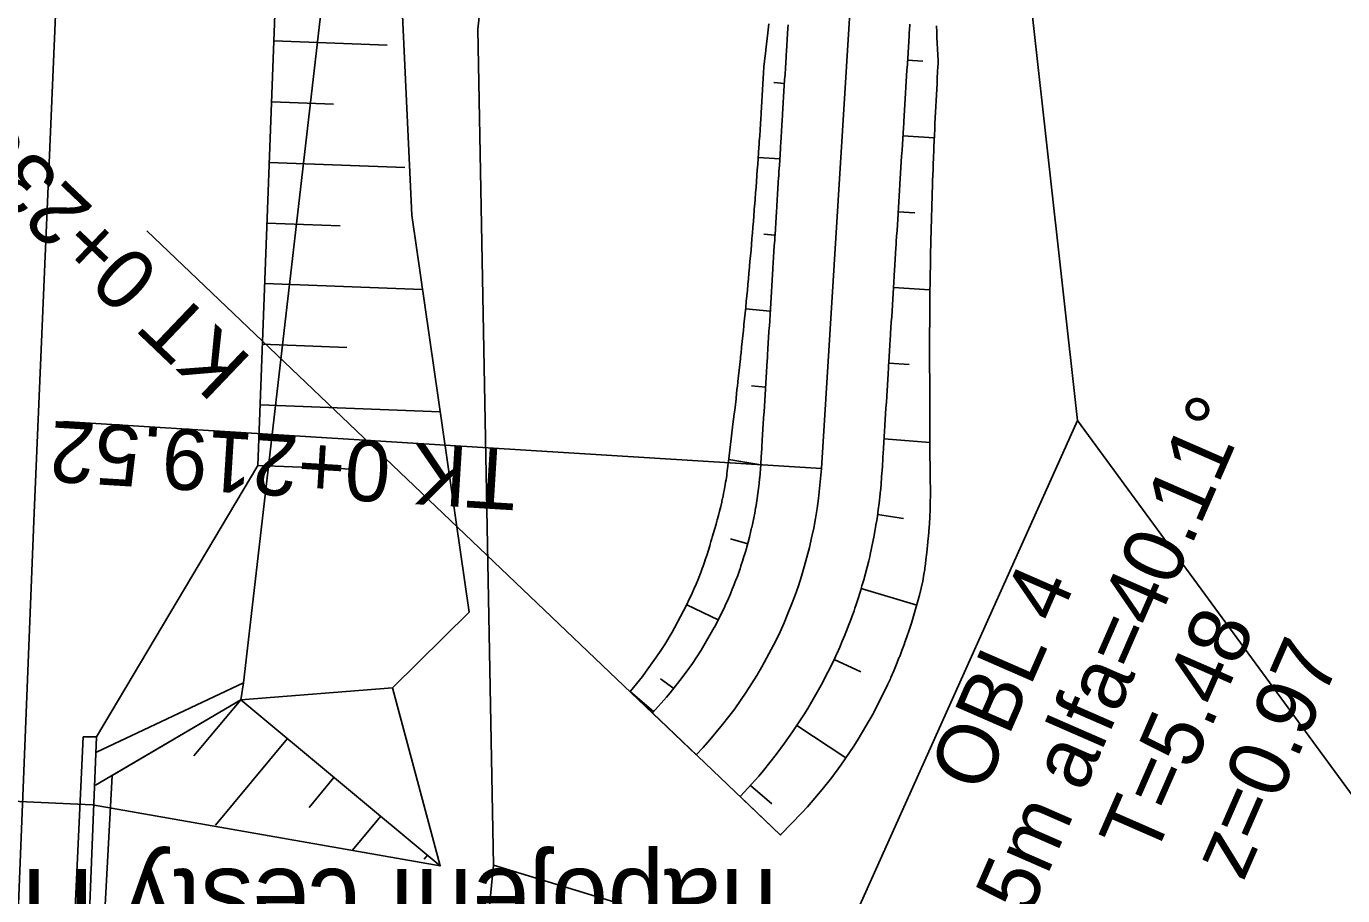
# Model space of a CAD drawing. Extents: x -583470 to -583050, y -1165714 to -1165417.
# Drawn here: x -583387.17 to -583343.82, y -1165639.09 to -1165610.45 of the extents above; entities that cross this region are included whole.
import ezdxf

# ---------------------------------------------------------------- set-up
doc = ezdxf.new("R2010")
doc.units = 0
for name, color, linetype in [('22', 7, 'Continuous'), ('40', 7, 'Continuous'), ('42', 7, 'Continuous'), ('60', 7, 'Continuous'), ('62', 7, 'Continuous'), ('Hranice parcel', 7, 'Continuous'), ('Parcelní čísla', 7, 'Continuous'), ('Rám', 7, 'Continuous'), ('Sítě', 7, 'Continuous'), ('Šrafy', 7, 'Continuous')]:
    doc.layers.add(name, color=color, linetype=linetype)

msp = doc.modelspace()

# ---------------------------------------------------------------- linework, layer by layer
at = {"layer": '22'}
for points in [[(-583384.86, -1165634.36), (-583380.02, -1165632.08), (-583380.11, -1165632.63), (-583384.89, -1165635.45)], [(-583385.3, -1165633.85), (-583384.86, -1165633.85), (-583385.19, -1165642.1), (-583385.68, -1165642.08), (-583385.3, -1165633.85)], [(-583384.99, -1165636.09), (-583389.58, -1165635.88)]]:
    msp.add_lwpolyline(points, dxfattribs=at)
at = {"layer": '40'}
msp.add_lwpolyline([(-583380.11, -1165632.63), (-583375.11, -1165632.24)], dxfattribs=at)
at = {"layer": '42'}
for points in [[(-583384.86, -1165633.85), (-583379.55, -1165624.92), (-583378.83, -1165605.97), (-583382.33, -1165599.28), (-583381.32, -1165575.74)], [(-583384.99, -1165636.09), (-583373.54, -1165638.1), (-583375.11, -1165632.24), (-583372.59, -1165629.75), (-583374.48, -1165616.67), (-583375, -1165605.38), (-583378.65, -1165593.33), (-583377.9, -1165588.81)], [(-583380.11, -1165632.63), (-583373.54, -1165638.1)]]:
    msp.add_lwpolyline(points, dxfattribs=at)
at = {"layer": '60'}
for points in [[(-583379.02, -1165610.93), (-583375.29, -1165611.07)], [(-583379.09, -1165612.93), (-583377.05, -1165613.01)], [(-583379.17, -1165614.93), (-583374.71, -1165615.1)], [(-583379.25, -1165616.93), (-583376.83, -1165617.02)], [(-583379.32, -1165618.92), (-583374.13, -1165619.12)], [(-583379.4, -1165620.92), (-583376.62, -1165621.03)], [(-583379.47, -1165622.92), (-583373.54, -1165623.15)], [(-583379.55, -1165624.92), (-583376.4, -1165625.04)], [(-583380.11, -1165632.63), (-583381.65, -1165634.48)], [(-583378.57, -1165633.91), (-583380.94, -1165636.76)], [(-583377.04, -1165635.19), (-583377.86, -1165636.18)], [(-583375.5, -1165636.47), (-583376.44, -1165637.6)], [(-583373.96, -1165637.75), (-583374.07, -1165637.88)]]:
    msp.add_lwpolyline(points, dxfattribs=at)
at = {"layer": '62'}
for points in [[(-583379.741, -1165694.56), (-583379.57, -1165690.87), (-583377.81, -1165675.52), (-583374, -1165654.25), (-583372.12, -1165641.43), (-583371.79, -1165638.08), (-583372.3, -1165610.54), (-583370.49, -1165593.91), (-583364.41, -1165578.01), (-583353.13, -1165562.49), (-583348.06, -1165556.64), (-583342.86, -1165548.6), (-583339.71, -1165538.95), (-583338.99, -1165532.81), (-583338.38, -1165526.75), (-583340.63, -1165516.91), (-583347.05, -1165504.24), (-583349.624, -1165498.549)], [(-583371.79, -1165638.08), (-583361.74, -1165641.15), (-583346.91, -1165644.58), (-583323.24, -1165647.92), (-583297.05, -1165651.52), (-583281.69, -1165654.07), (-583264.82, -1165656.96), (-583238.56, -1165662.27)]]:
    msp.add_lwpolyline(points, dxfattribs=at)
at = {"layer": 'Hranice parcel'}
for points in [[(-583365.111, -1165634.443), (-583383.196, -1165617.183)], [(-583360.991, -1165625.018), (-583385.943, -1165623.467)]]:
    msp.add_lwpolyline(points, dxfattribs=at)
at = {"layer": 'Parcelní čísla'}
msp.add_line((-583359.64, -1165603.276), (-583360.991, -1165625.018), dxfattribs=at)
msp.add_arc((-583375.962, -1165624.087), 15, 316.3365, 356.4435, dxfattribs=at)
at = {"layer": 'Rám'}
for points in [[(-583202.69, -1165538.68), (-583225.12, -1165531.51), (-583247.31, -1165545.19), (-583283.21, -1165574.06), (-583292.71, -1165580.22), (-583304.73, -1165581.14), (-583316.86, -1165578.96), (-583335.26, -1165581.29), (-583341.42, -1165583.09), (-583347.21, -1165586.62), (-583351.13, -1165592.35), (-583353.34, -1165595.85), (-583354.98, -1165601.64), (-583352.56, -1165623.43)], [(-583372.44, -1165649.28), (-583380.56, -1165643.71), (-583384.65, -1165640.82), (-583384.34, -1165635.13), (-583380.11, -1165632.63), (-583380.02, -1165632.08), (-583374.92, -1165587.93), (-583361.04, -1165570.69)], [(-583372.44, -1165649.28), (-583361.47, -1165643.29), (-583352.56, -1165623.43)], [(-583352.56, -1165623.43), (-583338.23, -1165642.98), (-583317.68, -1165646.22), (-583282.91, -1165650.36), (-583267.19, -1165652.43), (-583242.28, -1165656.94), (-583228.69, -1165666.2)]]:
    msp.add_lwpolyline(points, dxfattribs=at)
at = {"layer": 'Sítě'}
for points in [[(-583357.201, -1165610.434), (-583357.192, -1165610.624), (-583357.188, -1165610.705), (-583357.183, -1165610.814), (-583357.174, -1165611.004), (-583357.164, -1165611.194), (-583357.155, -1165611.384), (-583357.145, -1165611.574), (-583357.147, -1165611.709), (-583357.15, -1165611.763), (-583357.161, -1165611.952), (-583357.172, -1165612.14), (-583357.182, -1165612.329), (-583357.193, -1165612.518), (-583357.203, -1165612.708), (-583357.213, -1165612.896), (-583357.223, -1165613.084), (-583357.232, -1165613.273), (-583357.241, -1165613.462), (-583357.25, -1165613.651), (-583357.253, -1165613.707), (-583357.259, -1165613.84), (-583357.268, -1165614.029), (-583357.276, -1165614.218), (-583357.284, -1165614.407), (-583357.292, -1165614.596), (-583357.296, -1165614.706), (-583357.3, -1165614.785), (-583357.307, -1165614.974), (-583357.314, -1165615.163), (-583357.321, -1165615.352), (-583357.328, -1165615.541), (-583357.334, -1165615.705), (-583357.335, -1165615.73), (-583357.341, -1165615.919), (-583357.347, -1165616.108), (-583357.353, -1165616.297), (-583357.358, -1165616.486), (-583357.364, -1165616.675), (-583357.365, -1165616.705), (-583357.369, -1165616.864), (-583357.374, -1165617.053), (-583357.379, -1165617.242), (-583357.383, -1165617.431), (-583357.388, -1165617.621), (-583357.389, -1165617.706), (-583357.392, -1165617.81), (-583357.395, -1165617.999), (-583357.399, -1165618.188), (-583357.402, -1165618.377), (-583357.406, -1165618.567), (-583357.408, -1165618.707), (-583357.409, -1165618.756), (-583357.411, -1165618.945), (-583357.414, -1165619.135), (-583357.416, -1165619.324), (-583357.418, -1165619.513), (-583357.42, -1165619.708), (-583357.421, -1165619.892), (-583357.423, -1165620.081), (-583357.424, -1165620.271), (-583357.425, -1165620.46), (-583357.426, -1165620.649), (-583357.426, -1165620.709), (-583357.426, -1165620.839), (-583357.426, -1165621.028), (-583357.426, -1165621.218), (-583357.426, -1165621.407), (-583357.426, -1165621.596), (-583357.425, -1165621.711), (-583357.425, -1165621.786), (-583357.424, -1165621.975), (-583357.423, -1165622.165), (-583357.422, -1165622.354), (-583357.42, -1165622.544), (-583357.42, -1165622.714), (-583357.42, -1165622.733), (-583357.421, -1165622.923), (-583357.421, -1165623.112), (-583357.421, -1165623.302), (-583357.421, -1165623.491), (-583357.42, -1165623.681), (-583357.42, -1165623.716), (-583357.42, -1165623.87), (-583357.419, -1165624.06), (-583357.418, -1165624.249), (-583357.416, -1165624.439), (-583357.415, -1165624.628), (-583357.414, -1165624.718), (-583357.413, -1165624.818), (-583357.411, -1165625.007), (-583357.408, -1165625.197), (-583357.408, -1165625.24), (-583357.404, -1165625.422), (-583357.401, -1165625.657), (-583357.401, -1165625.837), (-583357.401, -1165625.893), (-583357.405, -1165626.129), (-583357.408, -1165626.248), (-583357.411, -1165626.366), (-583357.421, -1165626.602), (-583357.434, -1165626.839), (-583357.45, -1165627.075), (-583357.45, -1165627.087), (-583357.464, -1165627.258), (-583357.469, -1165627.312), (-583357.491, -1165627.548), (-583357.516, -1165627.785), (-583357.545, -1165628.021), (-583357.577, -1165628.257), (-583357.578, -1165628.268), (-583357.588, -1165628.338), (-583357.612, -1165628.493), (-583357.651, -1165628.729), (-583357.705, -1165628.961), (-583357.763, -1165629.192), (-583357.782, -1165629.265), (-583357.824, -1165629.422), (-583357.864, -1165629.567), (-583357.888, -1165629.652), (-583357.955, -1165629.881), (-583358.026, -1165630.109), (-583358.068, -1165630.242), (-583358.099, -1165630.336), (-583358.175, -1165630.562), (-583358.248, -1165630.768), (-583358.255, -1165630.787), (-583358.338, -1165631.01), (-583358.411, -1165631.202), (-583358.423, -1165631.233), (-583358.512, -1165631.455), (-583358.604, -1165631.675), (-583358.699, -1165631.895), (-583358.719, -1165631.94), (-583358.81, -1165632.141), (-583359.265, -1165633.054), (-583359.276, -1165633.073), (-583359.777, -1165633.936), (-583359.919, -1165634.16), (-583360.344, -1165634.784), (-583360.645, -1165635.192), (-583360.962, -1165635.594), (-583361.449, -1165636.164), (-583361.629, -1165636.362), (-583362.324, -1165637.067), (-583362.343, -1165637.085), (-583367.289, -1165632.364), (-583367.278, -1165632.352), (-583366.884, -1165631.862), (-583366.781, -1165631.726), (-583366.504, -1165631.343), (-583366.322, -1165631.076), (-583366.149, -1165630.808), (-583365.903, -1165630.403), (-583365.821, -1165630.259), (-583365.525, -1165629.708), (-583365.519, -1165629.696), (-583365.244, -1165629.12), (-583365.188, -1165628.994), (-583365.176, -1165628.965), (-583365.117, -1165628.828), (-583365.06, -1165628.69), (-583365.005, -1165628.552), (-583364.997, -1165628.532), (-583364.951, -1165628.412), (-583364.899, -1165628.273), (-583364.895, -1165628.261), (-583364.849, -1165628.132), (-583364.801, -1165627.991), (-583364.782, -1165627.933), (-583364.754, -1165627.85), (-583364.709, -1165627.708), (-583364.666, -1165627.565), (-583364.65, -1165627.512), (-583364.625, -1165627.422), (-583364.597, -1165627.324), (-583364.585, -1165627.278), (-583364.547, -1165627.134), (-583364.502, -1165626.992), (-583364.459, -1165626.849), (-583364.432, -1165626.754), (-583364.418, -1165626.706), (-583364.379, -1165626.561), (-583364.341, -1165626.417), (-583364.305, -1165626.271), (-583364.271, -1165626.126), (-583364.264, -1165626.092), (-583364.241, -1165625.987), (-583364.239, -1165625.979), (-583364.209, -1165625.832), (-583364.181, -1165625.685), (-583364.154, -1165625.537), (-583364.142, -1165625.463), (-583364.13, -1165625.389), (-583364.107, -1165625.241), (-583364.102, -1165625.205), (-583364.087, -1165625.092), (-583364.068, -1165624.942), (-583364.055, -1165624.827), (-583364.05, -1165624.784), (-583364.026, -1165624.596), (-583364.003, -1165624.408), (-583363.99, -1165624.309), (-583363.98, -1165624.22), (-583363.957, -1165624.032), (-583363.934, -1165623.844), (-583363.911, -1165623.656), (-583363.889, -1165623.468), (-583363.871, -1165623.315), (-583363.867, -1165623.28), (-583363.845, -1165623.092), (-583363.823, -1165622.904), (-583363.801, -1165622.716), (-583363.78, -1165622.528), (-583363.759, -1165622.339), (-583363.756, -1165622.32), (-583363.738, -1165622.151), (-583363.717, -1165621.963), (-583363.696, -1165621.775), (-583363.676, -1165621.587), (-583363.655, -1165621.399), (-583363.648, -1165621.325), (-583363.635, -1165621.211), (-583363.616, -1165621.022), (-583363.596, -1165620.834), (-583363.576, -1165620.646), (-583363.557, -1165620.458), (-583363.544, -1165620.329), (-583363.538, -1165620.269), (-583363.519, -1165620.081), (-583363.5, -1165619.893), (-583363.482, -1165619.705), (-583363.463, -1165619.516), (-583363.445, -1165619.328), (-583363.427, -1165619.14), (-583363.41, -1165618.951), (-583363.392, -1165618.763), (-583363.375, -1165618.575), (-583363.358, -1165618.386), (-583363.353, -1165618.337), (-583363.341, -1165618.198), (-583363.324, -1165618.009), (-583363.307, -1165617.821), (-583363.291, -1165617.633), (-583363.275, -1165617.444), (-583363.267, -1165617.341), (-583363.26, -1165617.256), (-583363.244, -1165617.067), (-583363.229, -1165616.879), (-583363.214, -1165616.69), (-583363.199, -1165616.502), (-583363.187, -1165616.344), (-583363.184, -1165616.313), (-583363.17, -1165616.125), (-583363.155, -1165615.936), (-583363.141, -1165615.748), (-583363.127, -1165615.559), (-583363.113, -1165615.37), (-583363.111, -1165615.346), (-583363.099, -1165615.182), (-583363.086, -1165614.993), (-583363.073, -1165614.805), (-583363.059, -1165614.616), (-583363.047, -1165614.427), (-583363.041, -1165614.349), (-583363.034, -1165614.239), (-583363.021, -1165614.05), (-583363.009, -1165613.861), (-583362.997, -1165613.673), (-583362.985, -1165613.484), (-583362.976, -1165613.351), (-583362.973, -1165613.295), (-583362.961, -1165613.107), (-583362.95, -1165612.918), (-583362.938, -1165612.729), (-583362.927, -1165612.54), (-583362.916, -1165612.352), (-583362.906, -1165612.163), (-583362.895, -1165611.974), (-583362.883, -1165611.785), (-583362.863, -1165611.597), (-583362.841, -1165611.409), (-583362.835, -1165611.356), (-583362.819, -1165611.221), (-583362.798, -1165611.033), (-583362.776, -1165610.845), (-583362.755, -1165610.657), (-583362.734, -1165610.469), (-583362.721, -1165610.361)], [(-583362.086, -1165610.4), (-583362.093, -1165610.508), (-583362.105, -1165610.697), (-583362.116, -1165610.886), (-583362.128, -1165611.075), (-583362.14, -1165611.263), (-583362.148, -1165611.399), (-583362.152, -1165611.452), (-583362.163, -1165611.641), (-583362.175, -1165611.829), (-583362.187, -1165612.018), (-583362.199, -1165612.207), (-583362.21, -1165612.396), (-583362.21, -1165612.397), (-583362.222, -1165612.584), (-583362.234, -1165612.773), (-583362.245, -1165612.962), (-583362.257, -1165613.15), (-583362.269, -1165613.339), (-583362.272, -1165613.395), (-583362.281, -1165613.528), (-583362.292, -1165613.717), (-583362.304, -1165613.905), (-583362.316, -1165614.094), (-583362.328, -1165614.283), (-583362.334, -1165614.393), (-583362.339, -1165614.471), (-583362.351, -1165614.66), (-583362.363, -1165614.849), (-583362.374, -1165615.037), (-583362.386, -1165615.226), (-583362.396, -1165615.391), (-583362.398, -1165615.415), (-583362.41, -1165615.604), (-583362.421, -1165615.792), (-583362.433, -1165615.981), (-583362.445, -1165616.17), (-583362.457, -1165616.358), (-583362.458, -1165616.389), (-583362.468, -1165616.547), (-583362.48, -1165616.736), (-583362.492, -1165616.925), (-583362.504, -1165617.113), (-583362.515, -1165617.302), (-583362.521, -1165617.387), (-583362.527, -1165617.491), (-583362.539, -1165617.679), (-583362.55, -1165617.868), (-583362.562, -1165618.057), (-583362.574, -1165618.246), (-583362.583, -1165618.385), (-583362.586, -1165618.434), (-583362.597, -1165618.623), (-583362.609, -1165618.812), (-583362.621, -1165619), (-583362.633, -1165619.189), (-583362.644, -1165619.378), (-583362.645, -1165619.383), (-583362.656, -1165619.566), (-583362.668, -1165619.755), (-583362.679, -1165619.944), (-583362.691, -1165620.133), (-583362.703, -1165620.321), (-583362.707, -1165620.381), (-583362.715, -1165620.51), (-583362.726, -1165620.699), (-583362.738, -1165620.887), (-583362.75, -1165621.076), (-583362.762, -1165621.265), (-583362.769, -1165621.379), (-583362.773, -1165621.454), (-583362.785, -1165621.642), (-583362.797, -1165621.831), (-583362.808, -1165622.02), (-583362.82, -1165622.208), (-583362.831, -1165622.377), (-583362.832, -1165622.397), (-583362.844, -1165622.586), (-583362.855, -1165622.775), (-583362.867, -1165622.963), (-583362.879, -1165623.152), (-583362.891, -1165623.341), (-583362.893, -1165623.375), (-583362.902, -1165623.529), (-583362.914, -1165623.718), (-583362.926, -1165623.907), (-583362.937, -1165624.095), (-583362.949, -1165624.284), (-583362.955, -1165624.373), (-583362.961, -1165624.473), (-583362.973, -1165624.662), (-583362.984, -1165624.85), (-583362.987, -1165624.894), (-583362.996, -1165625.02), (-583363.008, -1165625.183), (-583363.019, -1165625.307), (-583363.023, -1165625.346), (-583363.04, -1165625.509), (-583363.049, -1165625.591), (-583363.059, -1165625.672), (-583363.08, -1165625.834), (-583363.103, -1165625.997), (-583363.128, -1165626.159), (-583363.129, -1165626.167), (-583363.149, -1165626.283), (-583363.155, -1165626.32), (-583363.184, -1165626.481), (-583363.216, -1165626.642), (-583363.249, -1165626.803), (-583363.284, -1165626.963), (-583363.286, -1165626.97), (-583363.297, -1165627.017), (-583363.321, -1165627.122), (-583363.361, -1165627.281), (-583363.402, -1165627.44), (-583363.445, -1165627.598), (-583363.459, -1165627.648), (-583363.49, -1165627.756), (-583363.52, -1165627.854), (-583363.538, -1165627.912), (-583363.587, -1165628.069), (-583363.638, -1165628.224), (-583363.669, -1165628.316), (-583363.691, -1165628.379), (-583363.746, -1165628.534), (-583363.798, -1165628.675), (-583363.803, -1165628.687), (-583363.862, -1165628.84), (-583363.914, -1165628.971), (-583363.923, -1165628.992), (-583363.986, -1165629.144), (-583364.05, -1165629.294), (-583364.117, -1165629.444), (-583364.131, -1165629.475), (-583364.195, -1165629.612), (-583364.509, -1165630.238), (-583364.516, -1165630.251), (-583364.857, -1165630.845), (-583364.952, -1165631), (-583365.237, -1165631.433), (-583365.437, -1165631.718), (-583365.648, -1165632), (-583365.969, -1165632.402), (-583366.088, -1165632.543), (-583366.545, -1165633.049), (-583366.558, -1165633.063)], [(-583358.077, -1165610.379), (-583358.089, -1165610.568), (-583358.094, -1165610.649), (-583358.101, -1165610.757), (-583358.112, -1165610.945), (-583358.124, -1165611.134), (-583358.136, -1165611.323), (-583358.148, -1165611.511), (-583358.156, -1165611.647), (-583358.159, -1165611.7), (-583358.171, -1165611.889), (-583358.183, -1165612.078), (-583358.195, -1165612.266), (-583358.206, -1165612.455), (-583358.218, -1165612.644), (-583358.218, -1165612.645), (-583358.23, -1165612.832), (-583358.241, -1165613.021), (-583358.253, -1165613.21), (-583358.265, -1165613.399), (-583358.277, -1165613.587), (-583358.28, -1165613.643), (-583358.288, -1165613.776), (-583358.3, -1165613.965), (-583358.312, -1165614.153), (-583358.324, -1165614.342), (-583358.335, -1165614.531), (-583358.342, -1165614.641), (-583358.347, -1165614.719), (-583358.359, -1165614.908), (-583358.37, -1165615.097), (-583358.382, -1165615.286), (-583358.394, -1165615.474), (-583358.404, -1165615.639), (-583358.406, -1165615.663), (-583358.417, -1165615.852), (-583358.429, -1165616.04), (-583358.441, -1165616.229), (-583358.453, -1165616.418), (-583358.464, -1165616.607), (-583358.466, -1165616.637), (-583358.476, -1165616.795), (-583358.488, -1165616.984), (-583358.499, -1165617.173), (-583358.511, -1165617.361), (-583358.523, -1165617.55), (-583358.528, -1165617.635), (-583358.535, -1165617.739), (-583358.546, -1165617.928), (-583358.558, -1165618.116), (-583358.57, -1165618.305), (-583358.582, -1165618.494), (-583358.59, -1165618.633), (-583358.593, -1165618.682), (-583358.605, -1165618.871), (-583358.617, -1165619.06), (-583358.628, -1165619.248), (-583358.64, -1165619.437), (-583358.652, -1165619.626), (-583358.652, -1165619.631), (-583358.664, -1165619.815), (-583358.675, -1165620.003), (-583358.687, -1165620.192), (-583358.699, -1165620.381), (-583358.711, -1165620.569), (-583358.714, -1165620.629), (-583358.722, -1165620.758), (-583358.734, -1165620.947), (-583358.746, -1165621.136), (-583358.758, -1165621.324), (-583358.769, -1165621.513), (-583358.776, -1165621.627), (-583358.781, -1165621.702), (-583358.793, -1165621.89), (-583358.804, -1165622.079), (-583358.816, -1165622.268), (-583358.828, -1165622.457), (-583358.838, -1165622.625), (-583358.84, -1165622.645), (-583358.851, -1165622.834), (-583358.863, -1165623.023), (-583358.875, -1165623.211), (-583358.887, -1165623.4), (-583358.898, -1165623.589), (-583358.9, -1165623.624), (-583358.91, -1165623.777), (-583358.922, -1165623.966), (-583358.933, -1165624.155), (-583358.945, -1165624.344), (-583358.957, -1165624.532), (-583358.962, -1165624.622), (-583358.969, -1165624.721), (-583358.98, -1165624.91), (-583358.992, -1165625.098), (-583358.995, -1165625.142), (-583359.006, -1165625.306), (-583359.023, -1165625.52), (-583359.037, -1165625.683), (-583359.042, -1165625.734), (-583359.064, -1165625.947), (-583359.076, -1165626.053), (-583359.089, -1165626.16), (-583359.116, -1165626.372), (-583359.146, -1165626.584), (-583359.179, -1165626.796), (-583359.181, -1165626.807), (-583359.206, -1165626.959), (-583359.215, -1165627.007), (-583359.253, -1165627.218), (-583359.294, -1165627.428), (-583359.337, -1165627.638), (-583359.383, -1165627.848), (-583359.385, -1165627.857), (-583359.399, -1165627.919), (-583359.432, -1165628.056), (-583359.483, -1165628.264), (-583359.537, -1165628.472), (-583359.594, -1165628.678), (-583359.612, -1165628.744), (-583359.653, -1165628.884), (-583359.691, -1165629.013), (-583359.715, -1165629.089), (-583359.779, -1165629.294), (-583359.846, -1165629.497), (-583359.887, -1165629.617), (-583359.915, -1165629.7), (-583359.987, -1165629.902), (-583360.056, -1165630.086), (-583360.062, -1165630.103), (-583360.139, -1165630.303), (-583360.207, -1165630.474), (-583360.219, -1165630.502), (-583360.301, -1165630.7), (-583360.385, -1165630.897), (-583360.472, -1165631.092), (-583360.491, -1165631.133), (-583360.574, -1165631.313), (-583360.985, -1165632.13), (-583360.995, -1165632.148), (-583361.44, -1165632.925), (-583361.565, -1165633.127), (-583361.936, -1165633.694), (-583362.199, -1165634.066), (-583362.474, -1165634.434), (-583362.894, -1165634.961), (-583363.05, -1165635.145), (-583363.648, -1165635.807), (-583363.664, -1165635.824)]]:
    msp.add_lwpolyline(points, dxfattribs=at)
at = {"layer": 'Šrafy'}
for p, q in [((-583357.648, -1165611.596), (-583358.151, -1165611.565)), ((-583362.559, -1165612.302), (-583362.206, -1165612.331)), ((-583357.272, -1165614.124), (-583358.306, -1165614.06)), ((-583363.07, -1165614.767), (-583362.361, -1165614.817)), ((-583357.912, -1165616.589), (-583358.461, -1165616.555)), ((-583362.888, -1165617.291), (-583362.517, -1165617.322)), ((-583357.414, -1165619.125), (-583358.616, -1165619.051)), ((-583363.486, -1165619.75), (-583362.672, -1165619.83)), ((-583358.098, -1165621.588), (-583358.771, -1165621.546)), ((-583363.288, -1165622.287), (-583362.828, -1165622.339)), ((-583357.418, -1165624.152), (-583358.926, -1165624.041)), ((-583364.041, -1165624.719), (-583362.987, -1165624.891)), ((-583358.285, -1165626.661), (-583359.139, -1165626.531)), ((-583363.985, -1165627.326), (-583363.416, -1165627.491)), ((-583357.85, -1165629.518), (-583359.679, -1165628.97)), ((-583365.425, -1165629.5), (-583364.39, -1165630)), ((-583359.687, -1165631.717), (-583360.57, -1165631.303)), ((-583366.284, -1165631.946), (-583365.852, -1165632.256)), ((-583367.289, -1165632.364), (-583366.516, -1165633.018)), ((-583360.185, -1165634.55), (-583361.796, -1165633.479)), ((-583362.625, -1165636.056), (-583363.327, -1165635.452)), ((-583362.342, -1165637.084), (-583363.664, -1165635.824))]:
    msp.add_line(p, q, dxfattribs=at)
msp.add_lwpolyline([(-583389.634, -1165693.877), (-583387.68, -1165645.68), (-583386.91, -1165626.47), (-583385.88, -1165602.38), (-583384.78, -1165581.2), (-583382.27, -1165548.16), (-583380.06, -1165526.93), (-583377.27, -1165504.99), (-583376.322, -1165498.952)], dxfattribs=at)

# ---------------------------------------------------------------- texts
at = {"layer": 'Hranice parcel'}
for s, rotation, p in [('KT 0+230.02', 136.3365, (-583379.687, -1165621.436)), ('R=15m alfa=40.11%%d', 66.39, (-583356.145, -1165644.366)), ('TK 0+219.52', 176.4435, (-583370.972, -1165624.397)), ('OBL 4', 66.39, (-583355.662, -1165635.771)), ('  T=5.48', 66.39, (-583350.649, -1165639.283)), ('   z=0.97', 66.39, (-583347.993, -1165640.696))]:
    msp.add_text(s, height=2, rotation=rotation, dxfattribs=at).set_placement(p)
at = {"layer": 'Sítě'}
msp.add_text('napojení cesty HC5a na zpevněnou část M5', height=2.50002, rotation=180, dxfattribs=at).set_placement((-583362.443, -1165638.207))

doc.saveas('drawing.dxf')
